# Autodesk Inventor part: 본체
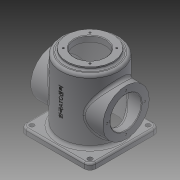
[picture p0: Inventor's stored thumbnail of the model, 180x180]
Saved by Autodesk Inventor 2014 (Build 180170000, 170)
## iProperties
Created: 2015-10
Part Number: 본체
Material: 일반
Document SubType Name: Modeling
Designer: Administrator
Density: 1 g/cm^3
Appearance: 기본값
Author: Administrator
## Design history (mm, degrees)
sketch "스케치1"
  geometry: L1 (-60, 60)-(60, 60); L2 (60, 60)-(60, -60); L3 (60, -60)-(-60, -60); L4 (-60, -60)-(-60, 60); 3 further points
  constraints: 8 end point, 2 midpoint, 2 parallel, 1 horizontal, 1 horizontal alignment, 1 perpendicular, 1 vertical alignment
  dimensions: "d0" = 120 distance between parallel lines of L2 L4; "d1" = 120 distance between parallel lines of L3 L1
extrude "돌출1" new body sketch "스케치1" distance "d2" = 10; taper "d3" = 0 deg
sketch "스케치7"
  geometry: C1 r 50 at (0, 0); 1 further point
  constraints: 1 centre point, 1 coincident
  dimensions: "d11" = 100 diameter of C1
extrude "돌출4" join sketch "스케치7" distance "d12" = 110; taper "d13" = 0 deg
sketch "스케치8"
  geometry: C1 r 40 at (0, 0); 1 further point
  constraints: 1 centre point, 1 coincident
  dimensions: "d14" = 80 diameter of C1
extrude "돌출5" join sketch "스케치8" distance "d15" = 5; taper "d16" = 0 deg
feature "쉘5" dims "d37" = 10, "d38" = 5
sketch "스케치9"
  geometry: C1 r 27 at (0, 0); 1 further point
  constraints: 1 centre point, 1 coincident
  dimensions: "d23" = 54 diameter of C1
extrude "돌출6" cut sketch "스케치9" stored distance "d24" = 5; taper "d25" = 0 deg
node "작업 평면4"
  node "작업 평면3"
sketch "스케치13"
  geometry: L1 (60, 0)-(-60, 0) reference; C1 r 40 at (0, 60); 2 further points
  constraints: 1 centre point, 1 midpoint, 1 vertical alignment
  dimensions: "d49" = 80 diameter of C1; "d50" = 60 distance from line of L1 C1.centre
extrude "돌출7" join sketch "스케치13" stored distance "d51" = 5; taper "d52" = 0 deg
sketch "스케치14" dims "d54" = 65
  geometry: L1 (0, 0)-(-40, 0); L2 (0, 0)-(-28.284, 28.284); A1 r 40 centre (0, 0) between (-40, 0) and (-28.284, 28.284) reference; 3 further points
  constraints: 4 end point, 2 point on circle, 1 coincident, 1 horizontal, 1 point on line, 3 other
  dimensions: "d53" = 45 deg angle of L1 L2
hole "구멍1" sketch "스케치14" at (-22.981, 22.981) diameter "d55" = 3.242; stored, may be unused: countersink angle "d59" = 90 deg, drill point angle "d61" = 118 deg; dims "d56" = 8, "d57" = 4, "d58" = 2, "d60" = 10
sketch "스케치16"
  geometry: L1 (60, 0)-(-60, 0) reference; C1 r 27 at (0, 60); 1 further point
  constraints: 1 centre point, 1 vertical alignment
  dimensions: "d66" = 54 diameter of C1; "d67" = 60 distance from line of L1 C1.centre
extrude "돌출8" cut sketch "스케치16" stored distance "d68" = 5; taper "d69" = 0 deg
sketch "스케치18"
  geometry: L1 (0, 0)-(-40, 0); 2 further points
  constraints: 2 end point, 1 horizontal alignment, 1 point on line, 1 other
  dimensions: "d71" = 32.5 distance of L1.start point (-32.5, 0)
hole "구멍2" sketch "스케치18" at (-32.5, 0) diameter "d72" = 3.242; stored, may be unused: countersink angle "d76" = 90 deg, drill point angle "d78" = 118 deg; dims "d73" = 8, "d74" = 4, "d75" = 2, "d77" = 10
fillet "모깎기1" dims "d82" = 3
chamfer "모따기1" distance "d83" = 3; stored, may be unused: second distance "d84" = 2, angle "d85" = 45 deg
chamfer "모따기2" distance "d86" = 1; stored, may be unused: second distance "d87" = 2, angle "d88" = 45 deg
fillet "모깎기3" dims "d90" = 5
fillet "모깎기4" dims "d91" = 5
fillet "모깎기5" dims "d92" = 3
sketch "스케치19"
  geometry: C1 r 4 at (-50, -50); 1 further point
  constraints: 1 centre point
  dimensions: "d93" = 8 diameter of C1; "d94" = 50 horizontal distance of point (0, 0) C1.centre; "d95" = 50 horizontal distance of C1.centre point (0, 0)
extrude "돌출9" cut sketch "스케치19" distance "d96" = 10; taper "d97" = 0 deg
node "작업 평면8"
  node "작업 평면7"
sketch "스케치21"
  geometry: L1 (60, 0)-(-60, 0) reference; 3 further points
  constraints: 1 midpoint, 1 vertical alignment, 1 other
  dimensions: "d112" = 70 distance from line of L1 point (0, 70)
feature "엠보싱2" sketch "스케치21" dims "d0" = 120, "d1" = 120, "d106" = 0.5, "d107" = 0
fillet "모깎기7" dims "d108" = 10
fillet "모깎기8" dims "d109" = 3
fillet "모깎기9" dims "d110" = 5
fillet "모깎기10" dims "d111" = 5
node "솔리드1"
pattern_circular "원형 패턴1" dims angle "d63" = 360 deg
pattern_circular "원형 패턴2" dims angle "d80" = 360 deg
mirror "대칭1"
mirror "대칭2"
mirror "대칭3"
other parameters: "d47" = 90 deg, "d48" = 62, "d104" = 90 deg, "d105" = 50.5
